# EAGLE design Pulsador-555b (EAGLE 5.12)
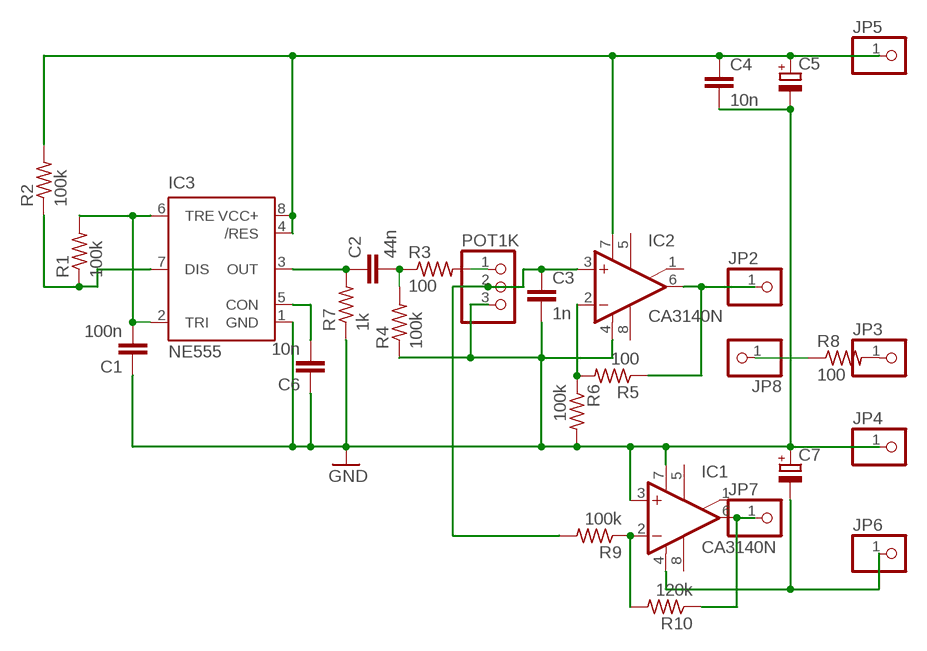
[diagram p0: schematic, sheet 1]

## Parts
C1  100n  C-EU050-024X044  [C050-024X044]
C2  44n  C-EU050-024X044  [C050-024X044]
C3  1n  C-EU050-024X044  [C050-024X044]
C4  10n  C-EU025-025X050  [C025-025X050]
C5  CPOL-EUE2.5-6  [E2,5-6]
C6  10n  C-EU050-024X044  [C050-024X044]
C7  CPOL-EUE2.5-6  [E2,5-6]
IC1  CA3140N  [DIL08]
IC2  CA3140N  [DIL08]
IC3  NE555  [DIL-08]
JP2  PINHD-1X1  [1X01]
JP3  PINHD-1X1  [1X01]
JP4  PINHD-1X1  [1X01]
JP5  PINHD-1X1  [1X01]
JP6  PINHD-1X1  [1X01]
JP7  PINHD-1X1  [1X01]
JP8  PINHD-1X1  [1X01]
POT1K  PINHD-1X3  [1X03]
R1  100k  R-US_0204/7  [0204/7]
R2  100k  R-US_0204/7  [0204/7]
R3  100  R-US_0204/7  [0204/7]
R4  100k  R-US_0204/7  [0204/7]
R5  100  R-US_0204/7  [0204/7]
R6  100k  R-US_0204/7  [0204/7]
R7  1k  R-US_0204/7  [0204/7]
R8  100  R-US_0204/7  [0204/7]
R9  100k  R-US_0204/7  [0204/7]
R10  120k  R-US_0204/7  [0204/7]

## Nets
GND: C1.1 C3.2 C4.2 C5.- C6.1 C7.+ IC1.3(+IN) IC1.7(V+) IC2.4(V-) IC3.1(GND) JP4.1 POT1K.3 R4.1 R6.2 R7.1
N$1: IC1.2(-IN) R9.1 R10.2
N$2: C6.2 IC3.5(CON)
N$3: C2.1 IC3.3(OUT) R7.2
N$4: C2.2 R3.1 R4.2
N$5: C3.1 IC2.3(+IN) POT1K.2 R9.2
N$6: POT1K.1 R3.2
N$7: IC2.6(OUT) JP2.1 R5.1
N$8: IC2.2(-IN) R5.2 R6.1
N$9: IC3.7(DIS) R1.1 R2.1
N$10: C4.1 C5.+ IC2.7(V+) IC3.4(/RES) IC3.8(VCC+) JP5.1 R2.2
N$11: C1.2 IC3.2(TRI) IC3.6(TRE) R1.2
N$12: JP3.1 R8.2
N$13: IC1.6(OUT) JP7.1 R10.1
N$14: JP8.1 R8.1
N$15: C7.- IC1.4(V-) JP6.1
Unconnected: IC1.1(ON/CMP) IC1.5(ON) IC1.8(CMP) IC2.1(ON/CMP) IC2.5(ON) IC2.8(CMP)

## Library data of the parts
C1-C4 C6 = rcl:C-EU: CAPACITOR, European symbol
C5 C7 = rcl:CPOL-EU: POLARIZED CAPACITOR, European symbol
IC1 IC2 = linear:CA3140: OP AMP
IC3 = st-microelectronics:NE555: General purpose bipolar Timer; MF: Arrow Electronics; MPN: NE555N; OC_FARNELL: 1467742; OC_NEWARK: 89K1486
JP2-JP8 = pinhead:PINHD-1X1: PIN HEADER
POT1K = pinhead:PINHD-1X3: PIN HEADER
R1-R10 = rcl:R-US_: RESISTOR, American symbol

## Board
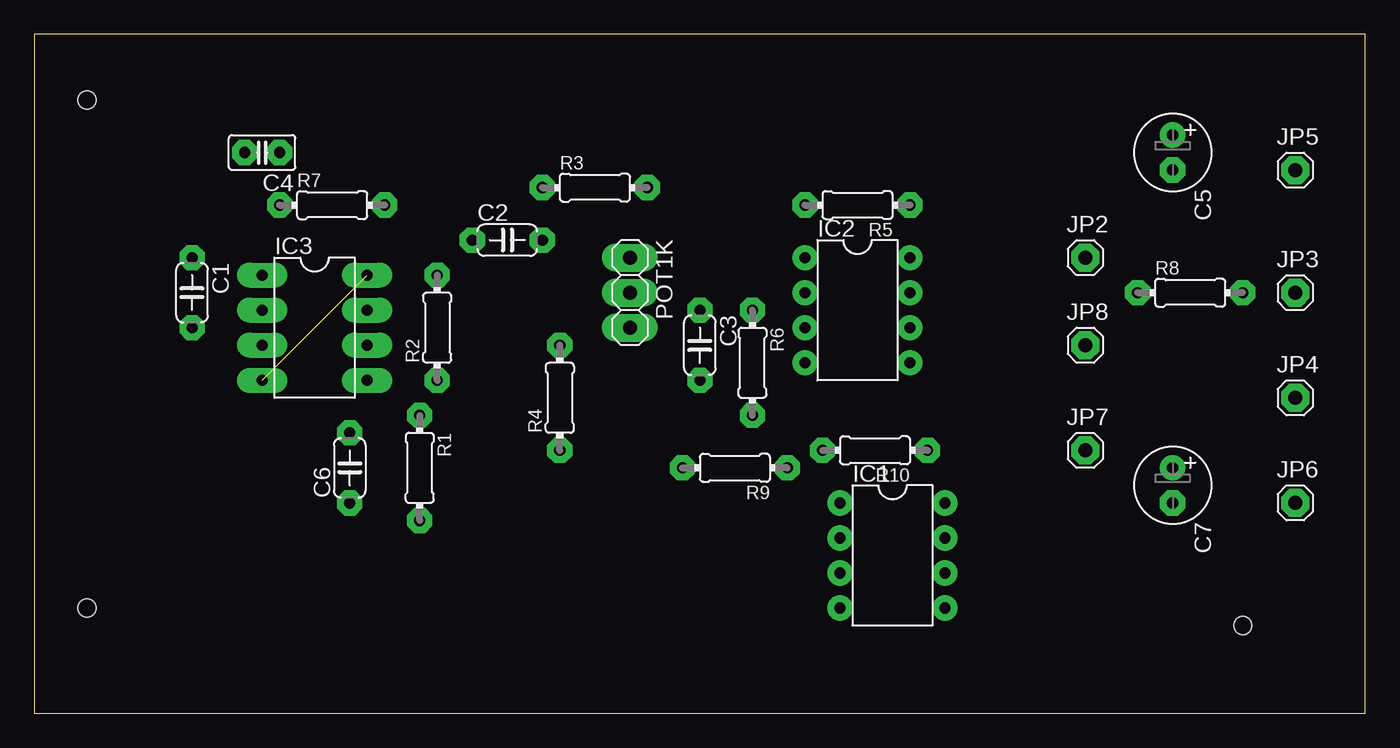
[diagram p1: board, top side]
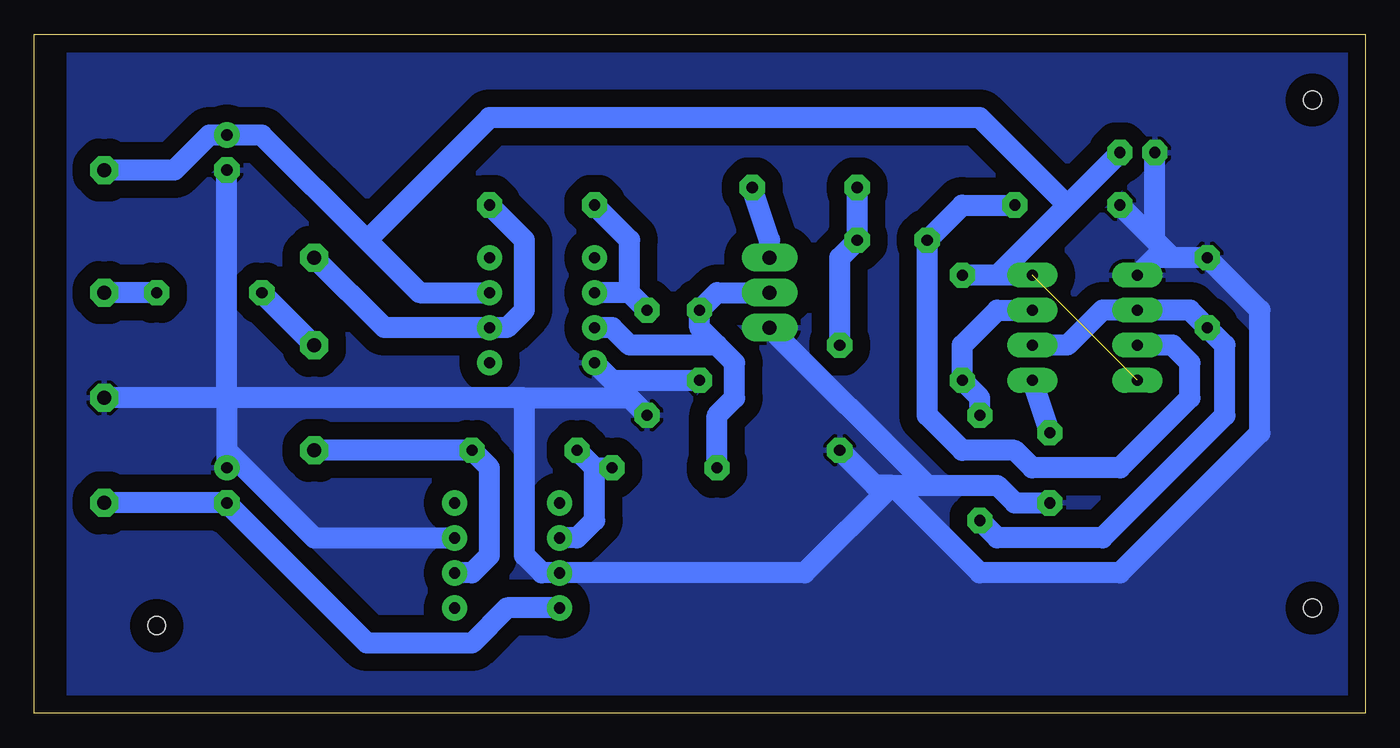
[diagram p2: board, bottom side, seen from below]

Size 96.5 x 49.2 mm. Coordinates in mm from the lower left corner, seen from the top.
Outline: 0,0 96.5,0 96.5,49.2 0,49.2 0,0
Copper layers (1*16): Top 0.035mm / dielectric 1.5mm / Bottom 0.035mm
Design rules "default *": minimum track width 60mil, minimum drill 24mil, track to track 20mil, track to pad 20mil, pad to pad 8mil, via to via 8mil, smd to smd 8mil, copper to edge 40mil, drill to drill 8mil, minimum pad ring 20mil, minimum via ring 8mil, stop-mask expansion 4mil, vias tented up to drill 0mil, thermal gap 10mil
Holes 1.3 mm at 3.81,44.45 3.81,7.62 87.63,6.35

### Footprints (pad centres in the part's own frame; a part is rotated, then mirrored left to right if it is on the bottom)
C050-024X044 = drill 0.813 octagon: 1 -2.54,0; 2 2.54,0
C025-025X050 = drill 0.813 octagon: 1 -1.27,0; 2 1.27,0
E2,5-6 = drill 0.813 pad 1.6 round: + -1.27,0 | drill 0.813 pad 1.6 octagon: - 1.27,0
DIL08 = drill 0.813 pad 1.27 round: 1 -3.81,-3.81; 2 -1.27,-3.81; 3 1.27,-3.81; 4 3.81,-3.81; 5 3.81,3.81; 6 1.27,3.81; 7 -1.27,3.81; 8 -3.81,3.81
DIL-08 = drill 0.813 long: 1 -3.81,-3.81; 2 -1.27,-3.81; 3 1.27,-3.81; 4 3.81,-3.81; 5 3.81,3.81; 6 1.27,3.81; 7 -1.27,3.81; 8 -3.81,3.81
1X01 = drill 1.016 octagon: 1 0,0
1X03 = drill 1.016 long: 1 -2.54,0; 2 0,0; 3 2.54,0
0204/7 = drill 0.813 octagon: 1 -3.81,0; 2 3.81,0

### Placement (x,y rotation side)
C1  11.43,30.48 270 top
C2  34.29,34.29 0 top
C3  48.26,26.67 270 top
C4  16.51,40.64 180 top
C5  82.55,40.64 270 top
C6  22.86,17.78 90 top
C7  82.55,16.51 270 top
IC1  62.23,11.43 270 top
IC2  59.69,29.21 270 top
IC3  20.32,27.94 270 top
JP2  76.2,33.02 0 top
JP3  91.44,30.48 0 top
JP4  91.44,22.86 0 top
JP5  91.44,39.37 0 top
JP6  91.44,15.24 0 top
JP7  76.2,19.05 0 top
JP8  76.2,26.67 0 top
POT1K  43.18,30.48 270 top
R1  27.94,17.78 270 top
R2  29.21,27.94 90 top
R3  40.64,38.1 0 top
R4  38.1,22.86 90 top
R5  59.69,36.83 180 top
R6  52.07,25.4 270 top
R7  21.59,36.83 0 top
R8  83.82,30.48 0 top
R9  50.8,17.78 180 top
R10  60.96,19.05 180 top

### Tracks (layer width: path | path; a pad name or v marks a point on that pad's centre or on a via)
GND
  Bottom 1.524: 82.55,19.05 C7.+ | 82.55,22.86 82.55,19.05 | 82.55,22.86 C5.- | 82.55,22.86 JP4.1 | IC1.7 76.2,12.7 82.55,19.05 | 13.97,33.02 15.24,33.02 IC3.1 | 13.97,33.02 C1.1 7.62,29.21 7.62,20.32 17.78,10.16 27.94,10.16 34.29,16.51 | 13.97,33.02 15.24,34.29 | 15.24,34.29 R7.1 | 15.24,34.29 C4.2 | 54.61,24.13 IC2.4 | 53.34,22.86 54.61,24.13 | 53.34,22.86 R6.2 | 54.61,24.13 C3.2 | 60.96,22.86 53.34,22.86 | 60.96,22.86 82.55,22.86 | 60.96,22.86 60.96,11.43 59.69,10.16 IC1.3 40.64,10.16 34.29,16.51 | C6.1 25.4,15.24 26.67,16.51 31.75,16.51 | 34.29,16.51 35.56,16.51 R4.1 | 34.29,16.51 31.75,16.51 | 31.75,16.51 POT1K.3
  pour Bottom (isolate 1.27): 0,1.27 0,48.26 93.98,48.26 93.98,1.27
N$1
  Bottom 1.524: 55.88,17.78 R9.1 | 55.88,17.78 R10.2 | IC1.2 57.15,12.7 55.88,13.97 55.88,17.78
N$2
  Bottom 1.524: C6.2 IC3.5
N$3
  Bottom 1.524: IC3.3 13.97,26.67 12.7,25.4 12.7,22.86 17.78,17.78 24.13,17.78 25.4,19.05 29.21,19.05 31.75,21.59 C2.1 29.21,36.83 R7.2
N$4
  Bottom 1.524: R4.2 38.1,33.02 C2.2 R3.1
N$5
  Bottom 1.524: POT1K.2 46.99,30.48 C3.1 48.26,27.94 46.99,26.67 | R9.2 46.99,21.59 45.72,22.86 45.72,25.4 46.99,26.67 | IC2.3 54.61,27.94 53.34,26.67 46.99,26.67
N$6
  Bottom 1.524: R3.2 43.18,34.29 POT1K.1
N$7
  Bottom 1.524: R5.1 60.96,34.29 60.96,29.21 62.23,27.94 IC2.6 71.12,27.94 JP2.1
N$8
  Bottom 1.524: R6.1 53.34,30.48 | 53.34,30.48 IC2.2 | R5.2 53.34,34.29 53.34,30.48
N$9
  Bottom 1.524: R1.1 27.94,22.86 R2.1 29.21,26.67 26.67,29.21 IC3.7
N$10  (1 unrouted)
  Bottom 1.524: JP5.1 86.36,39.37 83.82,41.91 C5.+ 80.01,41.91 72.39,34.29 | IC3.8 26.67,31.75 | 26.67,31.75 R2.2 | 26.67,31.75 21.59,36.83 | 21.59,36.83 C4.1 | IC2.7 68.58,30.48 72.39,34.29 | 21.59,36.83 27.94,43.18 63.5,43.18 72.39,34.29
N$11
  Bottom 1.524: R1.2 26.67,12.7 19.05,12.7 10.16,21.59 10.16,26.67 C1.2 12.7,29.21 IC3.2 19.05,29.21 21.59,26.67 IC3.6
N$12
  Bottom 1.524: R8.2 JP3.1
N$13
  Bottom 1.524: IC1.6 64.77,10.16 63.5,11.43 63.5,17.78 R10.1 JP7.1
N$14
  Bottom 1.524: JP8.1 R8.1
N$15
  Bottom 1.524: IC1.4 62.23,7.62 64.77,5.08 72.39,5.08 C7.- JP6.1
